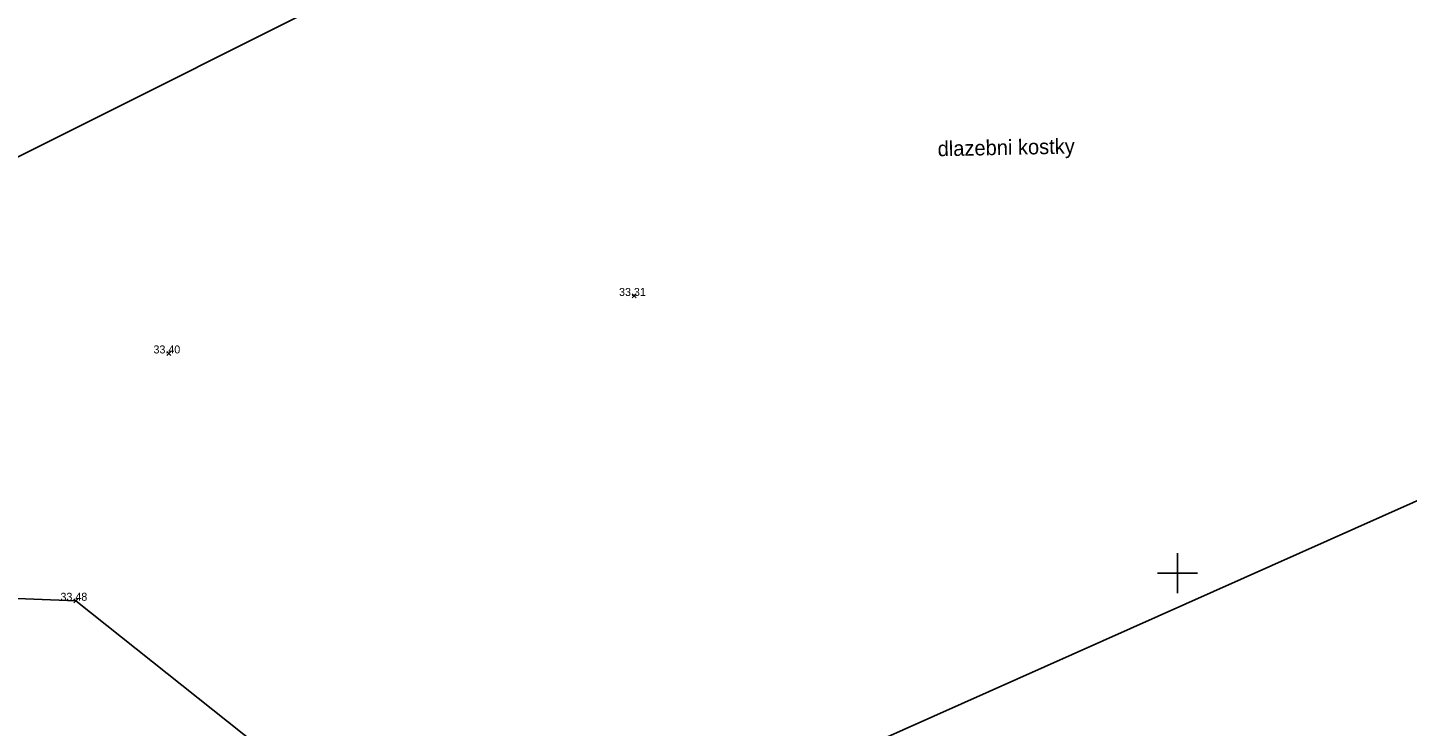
# Model space of a CAD drawing. Extents: x -772865 to -772533, y -1034366 to -1034132.
# Drawn here: x -772747.99 to -772720.4, y -1034278.06 to -1034264.08 of the extents above; entities that cross this region are included whole.
import ezdxf

# ---------------------------------------------------------------- set-up
doc = ezdxf.new("R2010")
doc.units = 0
for name, color, linetype in [('body', 7, 'Continuous'), ('mistni_popis', 7, 'Continuous'), ('oddeleni_ploch', 7, 'Continuous'), ('souradnicova_sit', 7, 'Continuous'), ('vyskove_koty', 7, 'Continuous')]:
    doc.layers.add(name, color=color, linetype=linetype)

msp = doc.modelspace()

# ---------------------------------------------------------------- linework, layer by layer
at = {"layer": 'body'}
for p, q in [((-772735.82, -1034269.49), (-772735.9, -1034269.41)), ((-772735.9, -1034269.49), (-772735.82, -1034269.41)), ((-772745.13, -1034270.64), (-772745.21, -1034270.56)), ((-772745.21, -1034270.64), (-772745.13, -1034270.56)), ((-772746.99, -1034275.59), (-772747.07, -1034275.51)), ((-772747.07, -1034275.59), (-772746.99, -1034275.51))]:
    msp.add_line(p, q, dxfattribs=at)
at = {"layer": 'oddeleni_ploch'}
for points in [[(-772569.67, -1034207.72), (-772578.35, -1034211.18), (-772588.33, -1034216.15), (-772592.11, -1034217.46), (-772598.89, -1034219.1), (-772610.21, -1034219.57), (-772621.14, -1034219.48), (-772637.34, -1034221.06), (-772647.54, -1034222.08), (-772674.34, -1034233.24), (-772685.01, -1034239.21), (-772697.33, -1034242.95), (-772712.12, -1034249.56), (-772725.85, -1034254.8), (-772738.85, -1034261.98), (-772750.37, -1034267.76), (-772764, -1034272.65), (-772783.9, -1034280.59), (-772796.38, -1034286.28), (-772810.31, -1034291.67), (-772823.61, -1034294.35), (-772828.52, -1034296.12), (-772827.01, -1034302.81), (-772823.23, -1034300.75)], [(-772689.63, -1034259.88), (-772704.53, -1034266.45), (-772719.18, -1034273.09), (-772731.59, -1034278.63), (-772738.33, -1034281.57), (-772742.46, -1034279.19), (-772747.03, -1034275.55), (-772755.44, -1034275.22), (-772763.58, -1034277.24), (-772782.03, -1034284.79), (-772793.82, -1034291.56), (-772799.88, -1034296.39), (-772802.42, -1034299.52), (-772804.8, -1034304.37)]]:
    msp.add_lwpolyline(points, dxfattribs=at)
at = {"layer": 'souradnicova_sit'}
for p, q in [((-772725, -1034274.6), (-772725, -1034275.4)), ((-772725.4, -1034275), (-772724.6, -1034275))]:
    msp.add_line(p, q, dxfattribs=at)

# ---------------------------------------------------------------- texts
at = {"layer": 'mistni_popis'}
msp.add_text('dlazebni kostky', height=0.3, rotation=1.1459, dxfattribs=at).set_placement((-772729.791, -1034266.654))
at = {"layer": 'vyskove_koty'}
for s, p in [('33.31', (-772736.165, -1034269.45)), ('33.40', (-772745.475, -1034270.6)), ('33.48', (-772747.335, -1034275.55))]:
    msp.add_text(s, height=0.16, dxfattribs=at).set_placement(p)

doc.saveas('drawing.dxf')
